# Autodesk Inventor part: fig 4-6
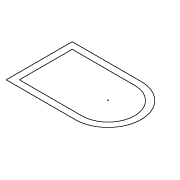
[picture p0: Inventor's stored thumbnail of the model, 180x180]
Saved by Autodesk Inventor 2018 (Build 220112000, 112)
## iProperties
Created: 2005-02
Part Number: fig 4-6
Document SubType Name: Modeling
Designer: CADCIM
Manufacturer: Standard
Standards Organization: Custom
Density: 1 g/cm^3
Material: Generic
Appearance: Default
Author: CADCIM
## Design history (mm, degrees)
sketch "Sketch1"
  geometry: L1 (12.963, 23.563)-(-25.99, 23.563); L2 (-25.99, 23.563)-(-25.99, -13.729); L3 (-25.99, -13.729)-(12.963, -13.729); L4 (-22.275, 19.848)-(12.963, 19.848); L5 (12.963, -10.014)-(-22.275, -10.014); L6 (-22.275, -10.014)-(-22.275, 19.848); A1 r 18.646 centre (12.963, 4.917) between (12.963, -13.729) and (12.963, 23.563); A2 r 14.931 centre (12.963, 4.917) between (12.963, -10.014) and (12.963, 19.848)
  constraints: 12 end point, 4 point on circle, 2 centre point, 2 parallel, 2 perpendicular, 2 tangent, 1 horizontal, 4 other
